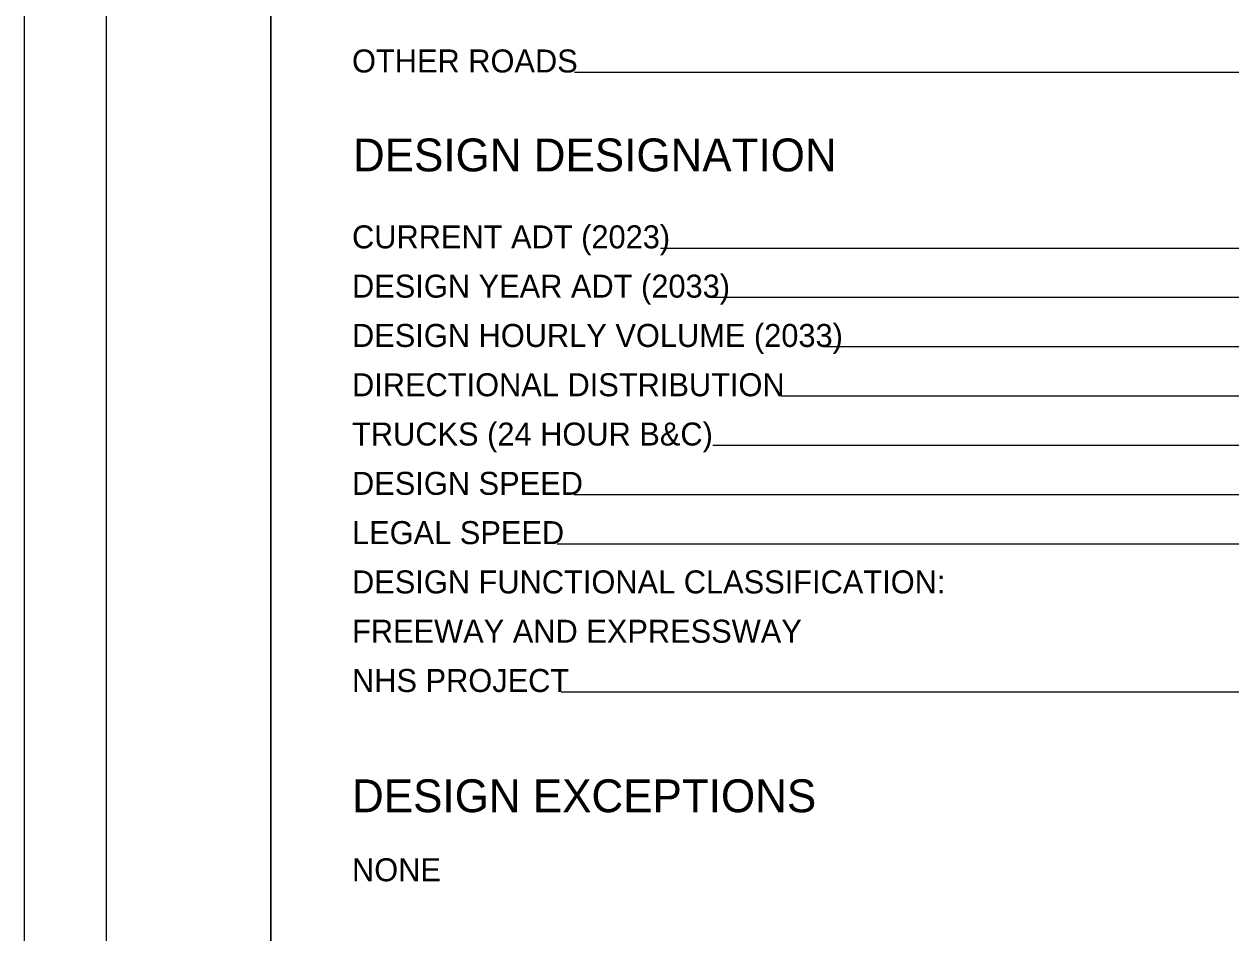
# Model space of a CAD drawing. Extents: x 0 to 51, y -1.2 to 22.
# Drawn here: x 0 to 7.34, y 5.64 to 11.17 of the extents above; entities that cross this region are included whole.
import ezdxf

# ---------------------------------------------------------------- set-up
doc = ezdxf.new("R2010")
doc.units = 0
for name, color, linetype in [('SH_Border', 7, 'Continuous'), ('SH_Cut_Line', 7, 'Continuous'), ('SH_Text', 7, 'Continuous')]:
    doc.layers.add(name, color=color, linetype=linetype)

msp = doc.modelspace()

# ---------------------------------------------------------------- linework, layer by layer
at = {"layer": 'SH_Border'}
for points in [[(0.5, 21.5), (1.5, 21.5), (1.5, 0.5), (0.5, 0.5)], [(1.5, 21.5), (33.5, 21.5), (33.5, 0.5), (1.5, 0.5)]]:
    msp.add_lwpolyline(points, close=True, dxfattribs=at)
at = {"layer": 'SH_Cut_Line'}
msp.add_lwpolyline([(0, 0), (34, 0), (34, 22), (0, 22)], close=True, dxfattribs=at)
at = {"layer": 'SH_Text'}
for p, q in [((7.7, 10.8767), (3.3471, 10.8767)), ((7.6424, 9.8062), (3.871, 9.8062)), ((7.6368, 9.5062), (4.1885, 9.5062)), ((7.6368, 9.2062), (4.8723, 9.2062)), ((7.6368, 8.9062), (4.6037, 8.9062)), ((7.6368, 8.6062), (4.1885, 8.6062)), ((7.6368, 8.3062), (3.346, 8.3062)), ((7.6368, 8.0062), (3.2422, 8.0062)), ((7.6368, 7.1062), (3.2669, 7.1062))]:
    msp.add_line(p, q, dxfattribs=at)

# ---------------------------------------------------------------- texts
for s, height, p in [('OTHER ROADS', 0.14, (1.9944, 10.8767)), ('DESIGN DESIGNATION', 0.2, (2, 10.2747)), ('CURRENT ADT (2023)', 0.14, (1.9944, 9.8062)), ('DESIGN YEAR ADT (2033)', 0.14, (1.9944, 9.5062)), ('DESIGN HOURLY VOLUME (2033)', 0.14, (1.9944, 9.2062)), ('DIRECTIONAL DISTRIBUTION', 0.14, (1.9944, 8.9062)), ('TRUCKS (24 HOUR B&C)', 0.14, (1.9944, 8.6062)), ('DESIGN SPEED', 0.14, (1.9944, 8.3062)), ('LEGAL SPEED', 0.14, (1.9944, 8.0062)), ('DESIGN FUNCTIONAL CLASSIFICATION:', 0.14, (1.9944, 7.7062)), ('FREEWAY AND EXPRESSWAY', 0.14, (1.9944, 7.4062)), ('NHS PROJECT', 0.14, (1.9944, 7.1062)), ('DESIGN EXCEPTIONS', 0.2, (1.9944, 6.3744)), ('NONE', 0.14, (1.9944, 5.9544))]:
    msp.add_text(s, height=height, dxfattribs=at).set_placement(p)

doc.saveas('drawing.dxf')
